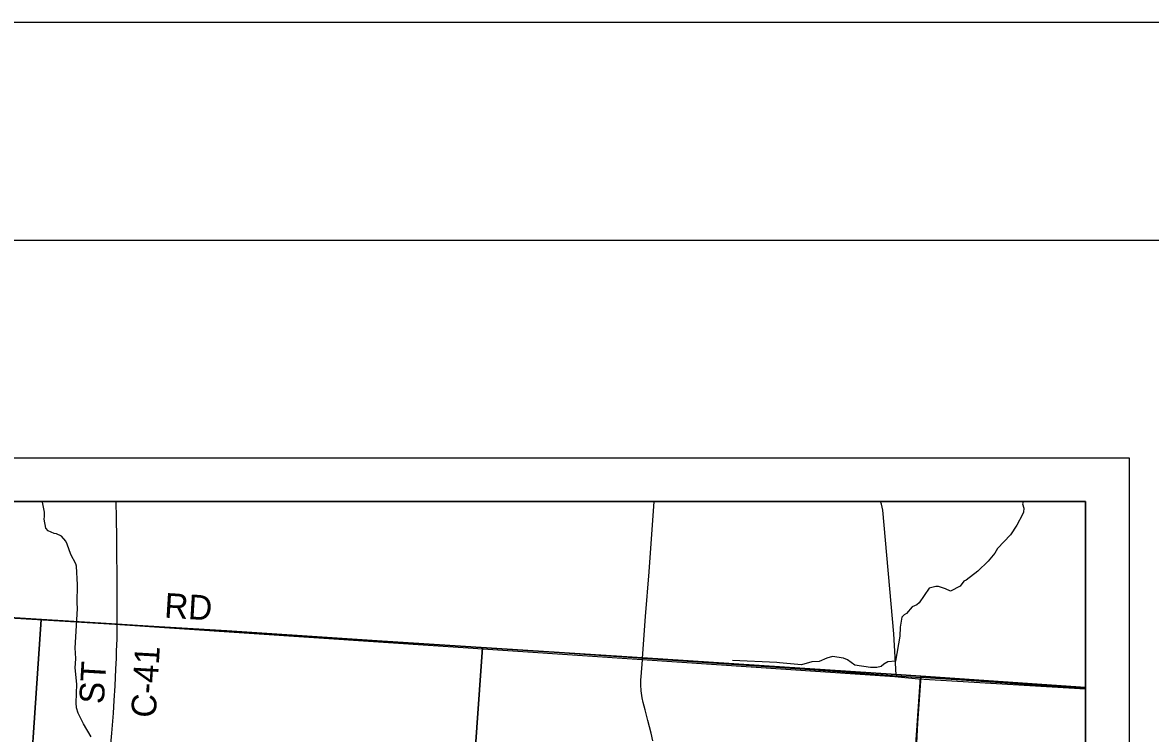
# Model space of a CAD drawing. Extents: x 0 to 34, y 0 to 22.
# Drawn here: x 6.46 to 9.049, y 20.367 to 22 of the extents above; entities that cross this region are included whole.
import ezdxf

# ---------------------------------------------------------------- set-up
doc = ezdxf.new("R2010")
doc.units = 0
for name, color, linetype in [('GM_X_Corporation', 7, 'Continuous'), ('GM_X_County_Road', 7, 'Continuous'), ('GM_X_County_Road_Text', 7, 'Continuous'), ('GM_X_Minor_River', 7, 'Continuous'), ('GM_X_Township_Road', 7, 'Continuous'), ('GM_X_Township_Road_Text', 7, 'Continuous'), ('SH_Border', 7, 'Continuous'), ('SH_Cut_Line', 7, 'Continuous'), ('SH_Data', 7, 'Continuous')]:
    doc.layers.add(name, color=color, linetype=linetype)

msp = doc.modelspace()

# ---------------------------------------------------------------- linework, layer by layer
at = {"layer": 'GM_X_Corporation'}
for points in [[(8.9, 20.4724), (8.9, 20.9), (4.3068, 20.9), (4.2973, 20.7554), (4.5367, 20.7456), (4.6201, 20.7441), (4.8574, 20.7216), (5.2396, 20.7003), (5.2473, 20.7005), (5.3653, 20.6955), (5.4957, 20.69), (5.8237, 20.6711), (6.676, 20.6183), (7.8827, 20.5405), (8.4655, 20.5021), (8.5224, 20.4984)], [(8.9, 20.4697), (8.9, 20.9), (5.3755, 20.9), (5.362, 20.6955), (5.3653, 20.6955), (5.4957, 20.69), (5.5024, 20.6884), (6.6719, 20.618), (7.8826, 20.5367), (8.4626, 20.4977), (8.5169, 20.4922)], [(5.4919, 20.6855), (5.8824, 20.6656), (6.3999, 20.6351), (6.5029, 20.629), (6.4654, 20.076), (5.9674, 20.1102), (5.4537, 20.1473)], [(6.5029, 20.629), (6.929, 20.6031), (7.5154, 20.5644), (7.4756, 20.0027), (6.9844, 20.0383), (6.4654, 20.076)], [(7.5154, 20.5644), (7.7109, 20.5519), (7.7144, 20.5517), (8.2347, 20.5164), (8.5204, 20.4957), (8.4813, 19.9336), (7.9967, 19.9667), (7.4756, 20.0027)], [(8.9, 19.9045), (8.9, 20.4692), (8.881, 20.4706), (8.6271, 20.4885), (8.5204, 20.4957), (8.4813, 19.9336)]]:
    msp.add_lwpolyline(points, close=True, dxfattribs=at)
for points in [[(6.0904, 18.0983), (6.5673, 18.064), (7.2487, 18.0119), (7.5344, 17.9901), (7.8447, 17.9665), (8.1742, 17.9461), (8.3494, 17.9349), (8.9, 17.9001), (8.9, 20.9), (4.3068, 20.9)], [(6.0906, 18.0978), (6.5646, 18.0583), (7.2489, 18.0114), (7.5346, 17.9896), (7.8449, 17.9659), (8.1744, 17.9455), (8.3496, 17.9344), (8.9, 17.8995), (8.9, 20.9), (4.3071, 20.9)], [(6.0904, 18.0983), (6.5673, 18.064), (7.2487, 18.0119), (7.5344, 17.9901), (7.8447, 17.9665), (8.1742, 17.9461), (8.3494, 17.9349), (8.9, 17.9001), (8.9, 20.4724), (8.5224, 20.4984), (8.4655, 20.5021), (7.8827, 20.5405), (6.676, 20.6183), (5.8237, 20.6711)]]:
    msp.add_lwpolyline(points, dxfattribs=at)
at = {"layer": 'GM_X_County_Road'}
for points in [[(6.6742, 20.9), (6.6747, 20.8618), (6.6752, 20.8161), (6.6757, 20.7812), (6.6765, 20.7292), (6.6764, 20.6717), (6.6762, 20.6178)], [(6.6762, 20.6178), (6.676, 20.5833), (6.6751, 20.5564), (6.6747, 20.5402), (6.6733, 20.5148), (6.6726, 20.4952), (6.6717, 20.4766), (6.6697, 20.4427), (6.6678, 20.4135), (6.6637, 20.3677), (6.6604, 20.3244)]]:
    msp.add_lwpolyline(points, dxfattribs=at)
at = {"layer": 'GM_X_Minor_River'}
for points in [[(6.6175, 20.3592), (6.5994, 20.3888), (6.5877, 20.4139), (6.584, 20.4257), (6.5832, 20.4371), (6.5841, 20.48), (6.5804, 20.5179), (6.5823, 20.5384), (6.5816, 20.5525), (6.5808, 20.5631), (6.5856, 20.6542), (6.5852, 20.6671), (6.5861, 20.7085), (6.5835, 20.7514), (6.5824, 20.7563), (6.5707, 20.778), (6.5624, 20.8019), (6.559, 20.8087), (6.5492, 20.8198), (6.5374, 20.8255), (6.5321, 20.8259), (6.5189, 20.8327), (6.5136, 20.8388), (6.5095, 20.8593), (6.5099, 20.8654), (6.5099, 20.8756), (6.5054, 20.898), (6.5056, 20.9)], [(8.7568, 20.9), (8.7551, 20.8945), (8.7585, 20.8846), (8.7581, 20.8755), (8.7551, 20.8698), (8.7421, 20.8452), (8.7277, 20.8232), (8.6977, 20.7918)], [(8.6977, 20.7918), (8.6916, 20.7811), (8.6765, 20.763), (8.6533, 20.7399), (8.6264, 20.719), (8.6211, 20.7164), (8.612, 20.7054), (8.59, 20.6937), (8.5786, 20.699), (8.5627, 20.7048), (8.5563, 20.7048), (8.5415, 20.7006), (8.5184, 20.6673), (8.513, 20.6624), (8.5024, 20.6575), (8.4895, 20.6427), (8.4835, 20.6397), (8.4785, 20.6344), (8.4747, 20.6108), (8.4735, 20.5907), (8.4636, 20.533), (8.4461, 20.5312), (8.437, 20.5259), (8.4313, 20.521), (8.4211, 20.5187), (8.4067, 20.5188), (8.3704, 20.5238), (8.3534, 20.536), (8.3443, 20.5401), (8.3193, 20.544), (8.306, 20.5402), (8.2886, 20.5319), (8.2719, 20.5316), (8.2484, 20.5244), (8.1977, 20.5295), (8.1913, 20.5299), (8.0894, 20.5347)]]:
    msp.add_lwpolyline(points, dxfattribs=at)
at = {"layer": 'GM_X_Township_Road'}
for p, q in [((8.5226, 20.4978), (8.4657, 20.5015)), ((8.9, 20.4719), (8.5226, 20.4978))]:
    msp.add_line(p, q, dxfattribs=at)
for points in [[(7.8829, 20.5399), (7.89, 20.6354), (7.8981, 20.738), (7.9095, 20.9)], [(8.4657, 20.5015), (8.4601, 20.5956), (8.4347, 20.88), (8.4319, 20.894), (8.4298, 20.9)], [(6.6762, 20.6178), (5.824, 20.6706), (5.4959, 20.6894)], [(8.4657, 20.5015), (7.8829, 20.5399), (6.6762, 20.6178)], [(7.9071, 20.3498), (7.903, 20.3679), (7.8953, 20.3966), (7.8889, 20.4212), (7.8845, 20.438), (7.8823, 20.4485), (7.8802, 20.4651), (7.8795, 20.4789), (7.8796, 20.4899), (7.88, 20.497), (7.8828, 20.5361), (7.8829, 20.5399)], [(8.4533, 19.4461), (8.4538, 19.4559), (8.4595, 19.5486), (8.4642, 19.6162), (8.4694, 19.6855), (8.4712, 19.7115), (8.4714, 19.7155), (8.4788, 19.8727), (8.4868, 19.9832), (8.4893, 19.9864), (8.491, 20.0087), (8.491, 20.017), (8.4943, 20.0681), (8.4934, 20.0737), (8.5073, 20.2393), (8.5154, 20.3909), (8.5226, 20.4978)]]:
    msp.add_lwpolyline(points, dxfattribs=at)
at = {"layer": 'SH_Border'}
msp.add_lwpolyline([(1.5, 21.5), (33.5, 21.5), (33.5, 0.5), (1.5, 0.5)], close=True, dxfattribs=at)
at = {"layer": 'SH_Cut_Line'}
msp.add_lwpolyline([(0, 0), (34, 0), (34, 22), (0, 22)], close=True, dxfattribs=at)
at = {"layer": 'SH_Data'}
for p, q in [((2, 21), (9, 21)), ((9, 21), (9, 14)), ((2.1, 20.9), (8.9, 20.9)), ((8.9, 20.9), (8.9, 14.1))]:
    msp.add_line(p, q, dxfattribs=at)

# ---------------------------------------------------------------- texts
at = {"layer": 'GM_X_County_Road_Text'}
for s, rotation, p in [('C-41', 86.6637, (6.7655, 20.4019)), ('ST', 86.604, (6.6463, 20.4336))]:
    msp.add_text(s, height=0.05682, rotation=rotation, dxfattribs=at).set_placement(p)
at = {"layer": 'GM_X_Township_Road_Text'}
msp.add_text('RD', height=0.05682, rotation=356.5467, dxfattribs=at).set_placement((6.7841, 20.6331))

doc.saveas('drawing.dxf')
